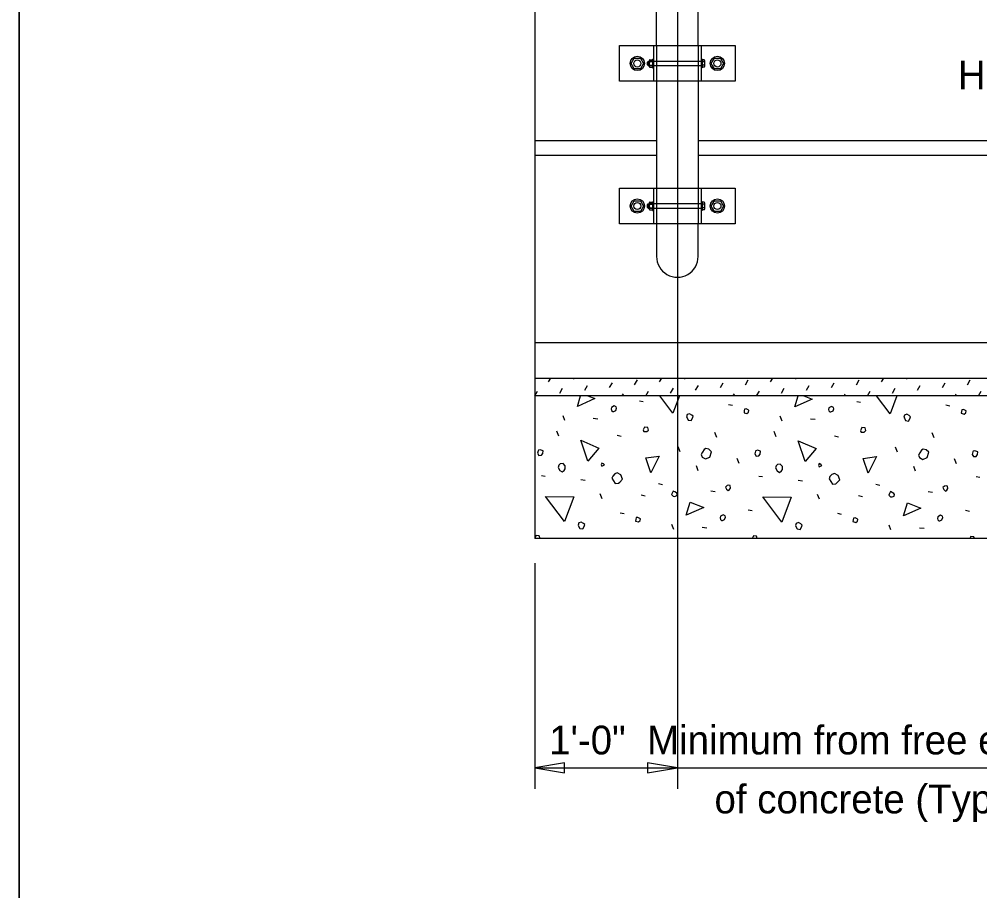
# Model space of a CAD drawing. Extents: x 0 to 41.1, y 0 to 25.9.
# Drawn here: x 0 to 6.74, y 10.96 to 17.07 of the extents above; entities that cross this region are included whole.
import ezdxf

# ---------------------------------------------------------------- set-up
doc = ezdxf.new("R2010")
doc.units = 0
for name, color, linetype in [('ActivePts-ConstElements', 7, 'Continuous'), ('CL_Major', 7, 'Continuous'), ('Dimension', 7, 'Continuous'), ('Miscellaneous', 7, 'Continuous'), ('Miscellaneous1', 7, 'Continuous'), ('SteelMisc', 7, 'Continuous'), ('SteelMisc_h', 7, 'Continuous'), ('SupstrConc', 7, 'Continuous'), ('SupstrConc_h', 7, 'Continuous'), ('TextStructures', 7, 'Continuous')]:
    doc.layers.add(name, color=color, linetype=linetype)

msp = doc.modelspace()

# ---------------------------------------------------------------- linework, layer by layer
at = {"layer": 'ActivePts-ConstElements'}
msp.add_lwpolyline([(0, 0), (41.0506, 0), (41.0506, 25.9461), (0, 25.9461)], close=True, dxfattribs=at)
msp.add_lwpolyline([(0, 0), (41.0506, 0), (41.0506, 25.9461), (0, 25.9461)], close=True, dxfattribs=at)
msp.add_lwpolyline([(0, 0), (41.0506, 0), (41.0506, 25.9461), (0, 25.9461)], close=True, dxfattribs=at)
at = {"layer": 'CL_Major'}
msp.add_line((4.615, 25.5927), (4.615, 11.6754), dxfattribs=at)
at = {"layer": 'Dimension'}
for p, q in [((3.615, 13.2594), (3.615, 11.6754)), ((3.6151, 11.8234), (8.3895, 11.8234))]:
    msp.add_line(p, q, dxfattribs=at)
for points in [[(3.6151, 11.8235), (3.8233, 11.7882), (3.8233, 11.8588)], [(4.6151, 11.8235), (4.4068, 11.8588), (4.4068, 11.7882)]]:
    msp.add_lwpolyline(points, close=True, dxfattribs=at)
at = {"layer": 'Miscellaneous'}
for p, q in [((4.4075, 16.7575), (4.4075, 16.7696)), ((4.4132, 16.7575), (4.4132, 16.7696)), ((4.4075, 15.7575), (4.4075, 15.7696)), ((4.4132, 15.7575), (4.4132, 15.7696)), ((3.7123, 14.5301), (3.7283, 14.5578)), ((3.8873, 14.5495), (3.8921, 14.5578)), ((4.4901, 14.5301), (4.5062, 14.5578)), ((4.6651, 14.5495), (4.6699, 14.5578)), ((5.2679, 14.5301), (5.284, 14.5578)), ((5.4429, 14.5495), (5.4477, 14.5578)), ((6.0457, 14.5301), (6.0618, 14.5578)), ((6.2207, 14.5495), (6.2255, 14.5578)), ((3.7901, 14.4523), (3.8095, 14.4859)), ((3.9651, 14.4717), (3.9845, 14.5053)), ((4.1401, 14.4912), (4.1595, 14.5248)), ((4.3151, 14.5106), (4.3345, 14.5442)), ((4.5679, 14.4523), (4.5873, 14.4859)), ((4.7429, 14.4717), (4.7623, 14.5053)), ((4.9179, 14.4912), (4.9373, 14.5248)), ((5.0929, 14.5106), (5.1123, 14.5442)), ((5.3457, 14.4523), (5.3651, 14.4859)), ((5.5207, 14.4717), (5.5401, 14.5053)), ((5.6957, 14.4912), (5.7152, 14.5248)), ((5.8707, 14.5106), (5.8902, 14.5442)), ((6.1235, 14.4523), (6.143, 14.4859)), ((6.2985, 14.4717), (6.318, 14.5053)), ((6.4735, 14.4912), (6.493, 14.5248)), ((6.6485, 14.5106), (6.668, 14.5442)), ((3.615, 14.4329), (3.6345, 14.4664)), ((4.2291, 14.4329), (4.2373, 14.447)), ((4.3929, 14.4329), (4.4123, 14.4664)), ((5.0069, 14.4329), (5.0151, 14.447)), ((5.1707, 14.4329), (5.1901, 14.4664)), ((5.7847, 14.4329), (5.7929, 14.447)), ((5.9485, 14.4329), (5.9679, 14.4664)), ((6.5626, 14.4329), (6.5708, 14.447)), ((6.7263, 14.4329), (6.7458, 14.4664)), ((4.3489, 14.3975), (4.3754, 14.3922)), ((4.9746, 14.3728), (5.0012, 14.3674)), ((5.8727, 14.394), (5.8992, 14.3887)), ((6.4985, 14.3692), (6.525, 14.3639)), ((3.8256, 14.2596), (3.8132, 14.2932)), ((5.3494, 14.2561), (5.337, 14.2897)), ((4.0254, 14.2755), (4.0572, 14.272)), ((5.5492, 14.272), (5.581, 14.2685)), ((3.7832, 14.15), (3.769, 14.1854)), ((4.1933, 14.1571), (4.2216, 14.15)), ((4.8916, 14.1412), (4.8774, 14.1765)), ((5.307, 14.1465), (5.2928, 14.1818)), ((5.7171, 14.1535), (5.7454, 14.1465)), ((6.4154, 14.1376), (6.4012, 14.173)), ((4.6352, 14.0404), (4.6211, 14.0758)), ((6.1591, 14.0369), (6.1449, 14.0722)), ((5.0489, 13.9591), (5.0348, 13.9944)), ((6.5727, 13.9556), (6.5586, 13.9909)), ((4.7607, 13.9078), (4.7484, 13.9414)), ((6.2846, 13.9043), (6.2722, 13.9379)), ((3.663, 13.8742), (3.6877, 13.8707)), ((3.9387, 13.846), (3.9688, 13.8407)), ((4.4832, 13.8177), (4.5115, 13.8106)), ((5.1868, 13.8707), (5.2115, 13.8672)), ((5.4626, 13.8424), (5.4926, 13.8371)), ((6.007, 13.8141), (6.0353, 13.8071)), ((6.7106, 13.8672), (6.7353, 13.8636)), ((4.0872, 13.7116), (4.0749, 13.7452)), ((4.8491, 13.7664), (4.8792, 13.7611)), ((5.611, 13.7081), (5.5987, 13.7417)), ((6.373, 13.7629), (6.403, 13.7576)), ((4.3612, 13.7381), (4.3895, 13.7311)), ((5.885, 13.7346), (5.9133, 13.7275)), ((3.615, 13.6321), (3.6152, 13.6321)), ((4.2145, 13.6126), (4.241, 13.6073)), ((5.1125, 13.6338), (5.1391, 13.6285)), ((5.7383, 13.6091), (5.7648, 13.6038)), ((6.6363, 13.6303), (6.6629, 13.625)), ((4.5893, 13.4959), (4.5769, 13.5295)), ((4.789, 13.5118), (4.8209, 13.5083)), ((6.1131, 13.4924), (6.1007, 13.526)), ((6.3128, 13.5083), (6.3447, 13.5048))]:
    msp.add_line(p, q, dxfattribs=at)
for points in [[(3.914, 14.3586), (3.9368, 14.4329)], [(3.9869, 14.4329), (4.036, 14.4134), (3.914, 14.3586)], [(4.584, 14.3109), (4.4913, 14.4329)], [(4.6296, 14.4329), (4.584, 14.3109)], [(5.4378, 14.3551), (5.4617, 14.4329)], [(5.5018, 14.4329), (5.5598, 14.4099), (5.4378, 14.3551)], [(6.1078, 14.3073), (6.0124, 14.4329)], [(6.1547, 14.4329), (6.1078, 14.3073)], [(4.1615, 14.3233), (4.1685, 14.3233), (4.1827, 14.3303), (4.188, 14.3462), (4.1862, 14.3551), (4.1721, 14.3621), (4.1544, 14.3515), (4.1509, 14.3409), (4.1544, 14.3303), (4.1615, 14.3233)], [(5.6853, 14.3197), (5.6924, 14.3197), (5.7065, 14.3268), (5.7118, 14.3427), (5.71, 14.3515), (5.6959, 14.3586), (5.6782, 14.348), (5.6747, 14.3374), (5.6782, 14.3268), (5.6853, 14.3197)], [(4.683, 14.2791), (4.6918, 14.2631), (4.713, 14.2596), (4.7219, 14.2755), (4.7254, 14.2897), (4.7166, 14.2985), (4.7006, 14.3073), (4.6847, 14.302), (4.6794, 14.2861), (4.683, 14.2791)], [(5.0825, 14.3144), (5.1019, 14.3091), (5.1143, 14.3179), (5.1161, 14.3303), (5.1125, 14.3339), (5.0984, 14.3409), (5.086, 14.3392), (5.0843, 14.3268), (5.0825, 14.3144)], [(6.2068, 14.2755), (6.2156, 14.2596), (6.2368, 14.2561), (6.2457, 14.272), (6.2492, 14.2861), (6.2404, 14.295), (6.2245, 14.3038), (6.2086, 14.2985), (6.2032, 14.2826), (6.2068, 14.2755)], [(6.6063, 14.3109), (6.6257, 14.3056), (6.6381, 14.3144), (6.6399, 14.3268), (6.6363, 14.3303), (6.6222, 14.3374), (6.6098, 14.3356), (6.6081, 14.3233), (6.6063, 14.3109)], [(4.3807, 14.1818), (4.4019, 14.1818), (4.4125, 14.1924), (4.4072, 14.2119), (4.3842, 14.2137), (4.3807, 14.203), (4.3754, 14.1942), (4.3807, 14.1818), (4.3771, 14.1854)], [(5.9045, 14.1783), (5.9257, 14.1783), (5.9363, 14.1889), (5.931, 14.2083), (5.908, 14.2101), (5.9045, 14.1995), (5.8992, 14.1907), (5.9045, 14.1783), (5.901, 14.1818)], [(3.9865, 13.975), (3.9387, 14.1217), (4.0642, 14.0669), (3.9865, 13.975)], [(5.5103, 13.9715), (5.4626, 14.1182), (5.5881, 14.0634), (5.5103, 13.9715)], [(3.6347, 14.0298), (3.6435, 14.0139), (3.663, 14.0157), (3.6718, 14.028), (3.6736, 14.0475), (3.6612, 14.0528), (3.6524, 14.0546), (3.6418, 14.051), (3.6382, 14.0475), (3.6347, 14.0298)], [(4.4284, 13.8937), (4.3948, 13.998), (4.4885, 14.0104), (4.4284, 13.8937)], [(4.789, 14.0033), (4.812, 13.9909), (4.8421, 14.0033), (4.8544, 14.0404), (4.8368, 14.0581), (4.8138, 14.0634), (4.8032, 14.0563), (4.7908, 14.0369), (4.782, 14.021), (4.789, 14.0033)], [(5.1585, 14.0263), (5.1673, 14.0104), (5.1868, 14.0121), (5.1956, 14.0245), (5.1974, 14.0439), (5.185, 14.0492), (5.1762, 14.051), (5.1656, 14.0475), (5.162, 14.0439), (5.1585, 14.0263)], [(6.3128, 13.9998), (6.3358, 13.9874), (6.3659, 13.9998), (6.3783, 14.0369), (6.3606, 14.0546), (6.3376, 14.0599), (6.327, 14.0528), (6.3146, 14.0333), (6.3058, 14.0174), (6.3128, 13.9998)], [(6.6823, 14.0227), (6.6912, 14.0068), (6.7106, 14.0086), (6.7194, 14.021), (6.7212, 14.0404), (6.7088, 14.0457), (6.7, 14.0475), (6.6894, 14.0439), (6.6858, 14.0404), (6.6823, 14.0227)], [(3.7796, 13.9308), (3.7902, 13.9096), (3.8079, 13.899), (3.8221, 13.9096), (3.8291, 13.9202), (3.8291, 13.9414), (3.8132, 13.9573), (3.7938, 13.9556), (3.7849, 13.9467), (3.7796, 13.9308)], [(4.0855, 13.9396), (4.1049, 13.9485), (4.0978, 13.9556), (4.0855, 13.9609), (4.0802, 13.9485), (4.0855, 13.9396)], [(5.3035, 13.9273), (5.3141, 13.9061), (5.3317, 13.8955), (5.3459, 13.9061), (5.353, 13.9167), (5.353, 13.9379), (5.337, 13.9538), (5.3176, 13.952), (5.3088, 13.9432), (5.3035, 13.9273)], [(5.6093, 13.9361), (5.6287, 13.945), (5.6217, 13.952), (5.6093, 13.9573), (5.604, 13.945), (5.6093, 13.9361)], [(5.9522, 13.8901), (5.9186, 13.9944), (6.0123, 14.0068), (5.9522, 13.8901)], [(4.1562, 13.8548), (4.1792, 13.8177), (4.2021, 13.8194), (4.211, 13.8283), (4.2304, 13.8477), (4.218, 13.8778), (4.1933, 13.8919), (4.1756, 13.8848), (4.1615, 13.8707), (4.1562, 13.8548)], [(5.68, 13.8513), (5.703, 13.8141), (5.7259, 13.8159), (5.7348, 13.8247), (5.7542, 13.8442), (5.7419, 13.8742), (5.7171, 13.8884), (5.6994, 13.8813), (5.6853, 13.8672), (5.68, 13.8513)], [(4.5857, 13.7293), (4.5981, 13.7275), (4.6105, 13.7328), (4.614, 13.7434), (4.6087, 13.7523), (4.5981, 13.7593), (4.5857, 13.7646), (4.5787, 13.7505), (4.5751, 13.7399), (4.5857, 13.7293)], [(4.9605, 13.7788), (4.9711, 13.7682), (4.9817, 13.7752), (4.9888, 13.7859), (4.9853, 13.8035), (4.9764, 13.8053), (4.964, 13.8035), (4.9534, 13.7929), (4.9605, 13.7788)], [(6.1096, 13.7257), (6.1219, 13.724), (6.1343, 13.7293), (6.1378, 13.7399), (6.1325, 13.7487), (6.1219, 13.7558), (6.1096, 13.7611), (6.1025, 13.747), (6.0989, 13.7364), (6.1096, 13.7257)], [(6.4843, 13.7752), (6.4949, 13.7646), (6.5055, 13.7717), (6.5126, 13.7823), (6.5091, 13.8), (6.5002, 13.8018), (6.4879, 13.8), (6.4773, 13.7894), (6.4843, 13.7752)], [(3.8238, 13.5507), (3.6895, 13.7275), (3.8892, 13.7257), (3.8238, 13.5507)], [(4.6777, 13.5949), (4.7059, 13.6869), (4.7996, 13.6497), (4.6777, 13.5949)], [(5.3476, 13.5472), (5.2133, 13.724), (5.4131, 13.7222), (5.3476, 13.5472)], [(6.2015, 13.5914), (6.2298, 13.6833), (6.3235, 13.6462), (6.2015, 13.5914)], [(3.9228, 13.5189), (3.9317, 13.503), (3.9529, 13.4995), (3.9617, 13.5154), (3.9653, 13.5295), (3.9564, 13.5384), (3.9405, 13.5472), (3.9246, 13.5419), (3.9193, 13.526), (3.9228, 13.5189)], [(4.3223, 13.5543), (4.3418, 13.549), (4.3542, 13.5578), (4.3559, 13.5702), (4.3524, 13.5737), (4.3383, 13.5808), (4.3259, 13.579), (4.3241, 13.5666), (4.3223, 13.5543)], [(4.9252, 13.5596), (4.9322, 13.5596), (4.9464, 13.5666), (4.9517, 13.5826), (4.9499, 13.5914), (4.9358, 13.5985), (4.9181, 13.5879), (4.9145, 13.5773), (4.9181, 13.5666), (4.9252, 13.5596)], [(5.4466, 13.5154), (5.4555, 13.4995), (5.4767, 13.4959), (5.4855, 13.5118), (5.4891, 13.526), (5.4802, 13.5348), (5.4643, 13.5437), (5.4484, 13.5384), (5.4431, 13.5225), (5.4466, 13.5154)], [(5.8462, 13.5507), (5.8656, 13.5454), (5.878, 13.5543), (5.8797, 13.5666), (5.8762, 13.5702), (5.8621, 13.5773), (5.8497, 13.5755), (5.8479, 13.5631), (5.8462, 13.5507)], [(6.449, 13.556), (6.456, 13.556), (6.4702, 13.5631), (6.4755, 13.579), (6.4737, 13.5879), (6.4596, 13.5949), (6.4419, 13.5843), (6.4384, 13.5737), (6.4419, 13.5631), (6.449, 13.556)], [(3.6522, 13.4328), (3.6471, 13.4517), (3.6241, 13.4535), (3.6205, 13.4429), (3.6152, 13.4341), (3.6158, 13.4328)], [(5.1751, 13.4328), (5.1709, 13.4482), (5.1479, 13.45), (5.1444, 13.4394), (5.1404, 13.4328)], [(6.6979, 13.4328), (6.6947, 13.4447), (6.6717, 13.4464), (6.6682, 13.4358), (6.6664, 13.4328)]]:
    msp.add_lwpolyline(points, dxfattribs=at)
at = {"layer": 'Miscellaneous1'}
msp.add_lwpolyline([(0, 25.9461), (41.0506, 25.9461), (41.0506, 0), (0, 0)], close=True, dxfattribs=at)
at = {"layer": 'SteelMisc'}
for p, q in [((4.4692, 16.8894), (4.4692, 17.3653)), ((4.7609, 16.8894), (4.7609, 17.3653)), ((4.2091, 16.8894), (5.021, 16.8894)), ((4.2091, 16.6394), (4.2091, 16.8894)), ((4.4484, 16.8894), (4.4484, 16.6394)), ((4.7817, 16.8894), (4.7817, 16.6394)), ((5.021, 16.8894), (5.021, 16.6394)), ((4.4047, 16.7724), (4.4103, 16.7789)), ((4.4047, 16.7547), (4.4047, 16.7724)), ((4.4103, 16.7789), (4.4168, 16.7789)), ((4.4103, 16.749), (4.4103, 16.7789)), ((4.4168, 16.7823), (4.4168, 16.7465)), ((4.4215, 16.7774), (4.4418, 16.7774)), ((4.4217, 16.7904), (4.4418, 16.7904)), ((4.4418, 16.7947), (4.4418, 16.734)), ((4.4418, 16.7947), (4.4484, 16.7947)), ((4.4418, 16.7904), (4.4418, 16.7384)), ((4.788, 16.7947), (4.782, 16.7947)), ((4.788, 16.7947), (4.788, 16.734)), ((4.8027, 16.7903), (4.788, 16.7903)), ((4.8028, 16.7773), (4.788, 16.7773)), ((4.8078, 16.745), (4.8078, 16.7838)), ((4.4047, 16.7547), (4.4103, 16.749)), ((4.4103, 16.749), (4.4168, 16.749)), ((4.4215, 16.7514), (4.4418, 16.7514)), ((4.4218, 16.7384), (4.4418, 16.7384)), ((4.4418, 16.734), (4.4484, 16.734)), ((4.788, 16.734), (4.782, 16.734)), ((4.8028, 16.7514), (4.788, 16.7514)), ((4.8027, 16.7384), (4.788, 16.7384)), ((5.021, 16.6394), (4.2091, 16.6394)), ((4.4692, 16.6394), (4.4692, 15.8894)), ((4.7609, 16.6394), (4.7609, 15.8894)), ((4.2091, 15.8894), (5.021, 15.8894)), ((4.2091, 15.6394), (4.2091, 15.8894)), ((4.4484, 15.8894), (4.4484, 15.6394)), ((4.7817, 15.8894), (4.7817, 15.6394)), ((5.021, 15.8894), (5.021, 15.6394)), ((4.4047, 15.7724), (4.4103, 15.7789)), ((4.4047, 15.7547), (4.4047, 15.7724)), ((4.4103, 15.7789), (4.4168, 15.7789)), ((4.4103, 15.749), (4.4103, 15.7789)), ((4.4168, 15.7823), (4.4168, 15.7465)), ((4.4215, 15.7774), (4.4418, 15.7774)), ((4.4217, 15.7904), (4.4418, 15.7904)), ((4.4418, 15.7947), (4.4418, 15.734)), ((4.4418, 15.7947), (4.4484, 15.7947)), ((4.4418, 15.7904), (4.4418, 15.7384)), ((4.788, 15.7947), (4.782, 15.7947)), ((4.788, 15.7947), (4.788, 15.734)), ((4.8027, 15.7903), (4.788, 15.7903)), ((4.8028, 15.7773), (4.788, 15.7773)), ((4.8078, 15.745), (4.8078, 15.7838)), ((4.4047, 15.7547), (4.4103, 15.749)), ((4.4103, 15.749), (4.4168, 15.749)), ((4.4215, 15.7514), (4.4418, 15.7514)), ((4.4218, 15.7384), (4.4418, 15.7384)), ((4.4418, 15.734), (4.4484, 15.734)), ((4.788, 15.734), (4.782, 15.734)), ((4.8028, 15.7514), (4.788, 15.7514)), ((4.8027, 15.7384), (4.788, 15.7384)), ((5.021, 15.6394), (4.2091, 15.6394)), ((4.4691, 15.6394), (4.4691, 15.4102)), ((4.7608, 15.4102), (4.7608, 15.6394))]:
    msp.add_line(p, q, dxfattribs=at)
for points in [[(4.3124, 16.8019), (4.3557, 16.8019), (4.3774, 16.7644), (4.3557, 16.7269), (4.3124, 16.7269), (4.2907, 16.7644)], [(4.8744, 16.8019), (4.9177, 16.8019), (4.9394, 16.7644), (4.9177, 16.7269), (4.8744, 16.7269), (4.8527, 16.7644)], [(4.3124, 15.8019), (4.3557, 15.8019), (4.3774, 15.7644), (4.3557, 15.7269), (4.3124, 15.7269), (4.2907, 15.7644)], [(4.8744, 15.8019), (4.9177, 15.8019), (4.9394, 15.7644), (4.9177, 15.7269), (4.8744, 15.7269), (4.8527, 15.7644)]]:
    msp.add_lwpolyline(points, close=True, dxfattribs=at)
for centre, radius in [((4.3341, 16.7644), 0.05), ((4.3341, 16.7644), 0.025), ((4.896, 16.7644), 0.05), ((4.896, 16.7644), 0.025), ((4.3341, 15.7644), 0.05), ((4.3341, 15.7644), 0.025), ((4.896, 15.7644), 0.05), ((4.896, 15.7644), 0.025)]:
    msp.add_circle(centre, radius, dxfattribs=at)
for centre, radius, start, end in [((4.4234, 16.7838), 0.00674, 104.48908, 254.18889), ((4.4363, 16.7644), 0.0196, 138.62797, 221.37203), ((4.801, 16.7838), 0.00673, 285.7823, 75.54039), ((4.7881, 16.7644), 0.0196, 318.62797, 41.37203), ((4.4234, 16.7449), 0.00673, 105.7823, 255.54039), ((4.801, 16.7449), 0.00674, 284.48908, 74.18889), ((4.4234, 15.7838), 0.00674, 104.48908, 254.18889), ((4.4363, 15.7644), 0.0196, 138.62797, 221.37203), ((4.801, 15.7838), 0.00673, 285.7823, 75.54039), ((4.7881, 15.7644), 0.0196, 318.62797, 41.37203), ((4.4234, 15.7449), 0.00673, 105.7823, 255.54039), ((4.801, 15.7449), 0.00674, 284.48908, 74.18889)]:
    msp.add_arc(centre, radius, start, end, dxfattribs=at)
msp.add_ellipse((4.615, 15.4102), major_axis=(0, 0.1458), ratio=0.999499, start_param=1.570796, end_param=4.712389, dxfattribs=at)
at = {"layer": 'SteelMisc_h'}
for p, q in [((4.4692, 16.8894), (4.4692, 16.6394)), ((4.7609, 16.8894), (4.7609, 16.6394)), ((4.7817, 16.7789), (4.4168, 16.7789)), ((4.4168, 16.749), (4.7817, 16.749)), ((4.4692, 15.8894), (4.4692, 15.6394)), ((4.7609, 15.8894), (4.7609, 15.6394)), ((4.7817, 15.7789), (4.4168, 15.7789)), ((4.4168, 15.749), (4.7817, 15.749))]:
    msp.add_line(p, q, dxfattribs=at)
at = {"layer": 'SupstrConc'}
for p, q in [((3.615, 17.2245), (3.615, 13.4328)), ((3.615, 16.2245), (4.4692, 16.2245)), ((4.7609, 16.2245), (14.4692, 16.2245)), ((3.615, 16.1203), (4.4692, 16.1203)), ((4.7609, 16.1203), (14.4692, 16.1203)), ((3.615, 14.5578), (16.002, 14.5578)), ((16.002, 14.4329), (3.615, 14.4329)), ((16.002, 13.4328), (3.615, 13.4328))]:
    msp.add_line(p, q, dxfattribs=at)
at = {"layer": 'SupstrConc_h'}
msp.add_line((3.615, 14.8078), (16.002, 14.8078), dxfattribs=at)

# ---------------------------------------------------------------- texts
at = {"layer": 'TextStructures'}
for s, p in [('Hog Rings @ 2\'-0" Centers', (6.5816, 16.5823)), ('1\'-0"  Minimum from free end ', (3.7161, 11.9179)), ('of concrete (Typ.)', (4.8754, 11.5043))]:
    msp.add_text(s, height=0.2016, dxfattribs=at).set_placement(p)

doc.saveas('drawing.dxf')
